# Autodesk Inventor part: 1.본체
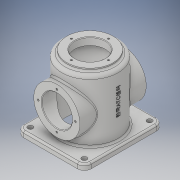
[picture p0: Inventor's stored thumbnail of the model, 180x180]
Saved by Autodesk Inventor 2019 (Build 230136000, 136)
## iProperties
Created: 2020-12
Part Number: 1.본체
Material: 일반
Document SubType Name: Modeling
Designer: jun-1-2
Density: 1 g/cm^3
Appearance: 기본값
Author: jun-1-2
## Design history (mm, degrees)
sketch "스케치1"
  geometry: L1 (-60, -70)-(60, -70); L2 (60, -70)-(60, 70); L3 (60, 70)-(-60, 70); L4 (-60, 70)-(-60, -70); L5 (-60, -70)-(60, 70); L6 (60, -70)-(-60, 70); 1 further point
  constraints: 12 end point, 2 midpoint, 2 parallel, 1 horizontal, 1 perpendicular
  dimensions: "d0" = 120 distance of L3.end L2.end; "d1" = 140 distance of L2.end L1.end
extrude "돌출1" new body sketch "스케치1" distance "d2" = 10; taper "d3" = 0 deg
fillet "모깎기1" dims "d4" = 12
sketch "스케치2"
  geometry: C1 r 50 at (0, 0); 1 further point
  constraints: 1 centre point, 1 coincident
  dimensions: "d5" = 100 diameter of C1
extrude "돌출2" join sketch "스케치2" distance "d6" = 110; taper "d7" = 0 deg
sketch "스케치3"
  geometry: C1 r 41 at (0, 0); 1 further point
  constraints: 1 centre point, 1 coincident
  dimensions: "d8" = 82 diameter of C1
extrude "돌출3" join sketch "스케치3" distance "d9" = 5; taper "d10" = 0 deg
sketch "스케치4"
  geometry: C1 r 42 at (0, 0); 1 further point
  constraints: 1 centre point, 1 coincident
  dimensions: "d11" = 84 diameter of C1
extrude "돌출4" cut sketch "스케치4" distance "d12" = 112; taper "d13" = 0 deg
sketch "스케치5"
  geometry: C1 r 27 at (0, 0); 1 further point
  constraints: 1 centre point, 1 coincident
  dimensions: "d14" = 54 diameter of C1
extrude "돌출5" cut sketch "스케치5" distance "d15" = 13; taper "d16" = 0 deg
sketch "스케치6"
  geometry: C1 r 41 at (0, 60); 1 further point
  constraints: 1 centre point, 1 vertical alignment
  dimensions: "d17" = 82 diameter of C1; "d18" = 60 distance of C1.centre point (0, 0)
extrude "돌출6" join sketch "스케치6" stored distance "d19" = 118; taper "d20" = 0 deg
sketch "스케치7"
  geometry: L1 (-48, -60)-(48, -60) reference; C1 r 27 at (0, 0); 2 further points
  constraints: 1 centre point, 1 midpoint, 1 vertical alignment
  dimensions: "d21" = 54 diameter of C1; "d22" = 60 distance from line of C1.centre L1
extrude "돌출7" cut sketch "스케치7" distance "d23" = 118; taper "d24" = 0 deg
sketch "스케치8"
  geometry: C1 r 42 at (0, 0) reference; 1 further point
extrude "돌출8" cut sketch "스케치8" distance "d25" = 112; taper "d26" = 0 deg
fillet "모깎기2" dims "d27" = 3
fillet "모깎기3" dims "d28" = 6
chamfer "모따기1" distance "d29" = 1; stored, may be unused: second distance "d30" = 2, angle "d31" = 45 deg
fillet "모깎기4" dims "d32" = 3
sketch "스케치9"
  geometry: A1 r 12 centre (48, -58) between (48, -70) and (60, -58) reference; 2 further points
  constraints: 1 coincident
hole "구멍1" sketch "스케치9" at (48, -58) diameter "d33" = 9; stored, may be unused: countersink angle "d37" = 90 deg, drill point angle "d39" = 0 deg; dims "d34" = 18, "d35" = 4, "d36" = 2, "d38" = 10
sketch "스케치10"
  geometry: A1 r 12 centre (48, 58) between (60, 58) and (48, 70) reference; 2 further points
  constraints: 1 coincident
hole "구멍2" sketch "스케치10" at (48, 58) diameter "d40" = 9; stored, may be unused: countersink angle "d44" = 90 deg, drill point angle "d46" = 0 deg; dims "d41" = 18, "d42" = 4, "d43" = 2, "d45" = 10
sketch "스케치11"
  geometry: A1 r 12 centre (-48, -58) between (-60, -58) and (-48, -70) reference; 2 further points
  constraints: 1 coincident
hole "구멍3" sketch "스케치11" at (-48, -58) diameter "d47" = 9; stored, may be unused: countersink angle "d51" = 90 deg, drill point angle "d53" = 0 deg; dims "d48" = 18, "d49" = 4, "d50" = 2, "d52" = 10
sketch "스케치12"
  geometry: A1 r 12 centre (-48, 58) between (-48, 70) and (-60, 58) reference; 2 further points
  constraints: 1 coincident
hole "구멍4" sketch "스케치12" at (-48, 58) diameter "d54" = 9; stored, may be unused: countersink angle "d58" = 90 deg, drill point angle "d60" = 0 deg; dims "d55" = 18, "d56" = 4, "d57" = 2, "d59" = 10
sketch "스케치13"
  geometry: L1 (42, -60)-(42, 49) reference; L2 (33, 0)-(-33, 0); L3 (0, -33)-(0, 33); C1 r 41 at (0, 0) reference; A1 r 33 centre (0, 0) between (33, 0) and (-33, 0); 5 further points
  constraints: 5 coincident, 4 end point, 4 point on circle, 1 centre point, 1 horizontal, 1 vertical
  dimensions: "d61" = 66 diameter of A1
hole "구멍5" sketch "스케치13" at (-33, 0), (0, -33), (0, 33), (33, 0) diameter "d62" = 3.242; stored, may be unused: countersink angle "d66" = 90 deg, drill point angle "d68" = 118 deg; dims "d63" = 8, "d64" = 4, "d65" = 2, "d67" = 10
sketch "스케치14"
  geometry: L1 (-33, 0)-(33, 0); L2 (0, -33)-(0, 33); A1 r 33 centre (0, 0) between (-33, 0) and (33, 0); 5 further points
  constraints: 5 coincident, 4 end point, 4 point on circle, 1 centre point, 1 horizontal, 1 perpendicular
  dimensions: "d69" = 66 diameter of A1
hole "구멍6" sketch "스케치14" at (0, 33), (-33, 0), (33, 0), (0, -33) diameter "d70" = 3.242; stored, may be unused: countersink angle "d74" = 90 deg, drill point angle "d76" = 118 deg; dims "d71" = 8, "d72" = 4, "d73" = 2, "d75" = 10
node "작업 평면1"
sketch "스케치15"
  geometry: L1 (-10, 58)-(-10, -58) reference; 3 further points
  constraints: 1 horizontal alignment, 1 midpoint, 1 other
  dimensions: "d77" = 70 distance from line of point (60, 0) L1
feature "엠보싱1" sketch "스케치15" dims "d0" = 120, "d1" = 140, "d9" = 5, "d10" = 0, "d78" = 0.5, "d79" = 0
node "솔리드1"
mirror "미러1"
